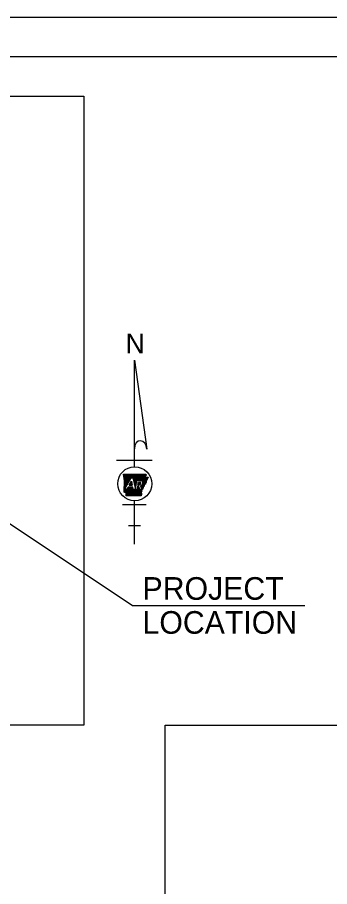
# Model space of a CAD drawing. Extents: x -0.25 to 1.92, y 0 to 0.95.
# Drawn here: x 0.3064 to 0.4721, y 0.4561 to 0.9167 of the extents above; entities that cross this region are included whole.
import ezdxf

# ---------------------------------------------------------------- set-up
doc = ezdxf.new("R2010")
doc.units = 0
for name, color, linetype in [('Default', 7, 'Continuous'), ('DSN_DRFT_DNC', 7, 'Continuous'), ('DSN_DRFT_Guideline-No-Plot', 7, 'Continuous'), ('Level 20', 7, 'Continuous'), ('Level 21', 7, 'Continuous'), ('SHET_Border-Lines', 7, 'Continuous')]:
    doc.layers.add(name, color=color, linetype=linetype)

msp = doc.modelspace()

# ---------------------------------------------------------------- linework, layer by layer
at = {"layer": 'Default'}
for q in [(0.17682, 0.73155), (0.45889, 0.60506)]:
    msp.add_line((0.36732, 0.60506), q, dxfattribs=at)
at = {"layer": 'DSN_DRFT_DNC'}
for points in [[(0.04167, 0.875), (0.34167, 0.875), (0.34167, 0.54167), (0.04167, 0.54167)], [(0.38477, 0.54167), (1.0319, 0.54167), (1.0319, 0.1443), (0.38477, 0.1443)]]:
    msp.add_lwpolyline(points, close=True, dxfattribs=at)
at = {"layer": 'DSN_DRFT_Guideline-No-Plot'}
msp.add_lwpolyline([(0, 0), (1.41667, 0), (1.41667, 0.91667), (0, 0.91667)], close=True, dxfattribs=at)
at = {"layer": 'Level 20'}
for p, q in [((0.3685, 0.73504), (0.37502, 0.68794)), ((0.3685, 0.67856), (0.3685, 0.73504)), ((0.35907, 0.68205), (0.37793, 0.68205)), ((0.36322, 0.66645), (0.36671, 0.6726)), ((0.36671, 0.6726), (0.36774, 0.6726)), ((0.36578, 0.66887), (0.36692, 0.67088)), ((0.36578, 0.66887), (0.36735, 0.66887)), ((0.36984, 0.67132), (0.37226, 0.67132)), ((0.37066, 0.66841), (0.37024, 0.66841)), ((0.37037, 0.66914), (0.3714, 0.66914)), ((0.37059, 0.67045), (0.37173, 0.67045)), ((0.37138, 0.66645), (0.37066, 0.66841)), ((0.37168, 0.66851), (0.37244, 0.66645)), ((0.36442, 0.66645), (0.36322, 0.66645)), ((0.36515, 0.66774), (0.36442, 0.66645)), ((0.36759, 0.66774), (0.36515, 0.66774)), ((0.3699, 0.66645), (0.36787, 0.66645)), ((0.37244, 0.66645), (0.37138, 0.66645)), ((0.3685, 0.63758), (0.3685, 0.6605)), ((0.36222, 0.65855), (0.37479, 0.65855)), ((0.36536, 0.64738), (0.37165, 0.64738))]:
    msp.add_line(p, q, dxfattribs=at)
for points in [[(0.36277, 0.67459), (0.36621, 0.67459), (0.36924, 0.6746), (0.3728, 0.67465), (0.37446, 0.67469)], [(0.36277, 0.6746), (0.36622, 0.67459), (0.36924, 0.6746), (0.3728, 0.67466), (0.37446, 0.67469)], [(0.36302, 0.66528), (0.36321, 0.67106), (0.36277, 0.6746)], [(0.36315, 0.66924), (0.36321, 0.67106), (0.36277, 0.67459)], [(0.36774, 0.6726), (0.36902, 0.66662), (0.36984, 0.67132)], [(0.37554, 0.67311), (0.37584, 0.6728), (0.37509, 0.67219), (0.37517, 0.67157), (0.37454, 0.67115), (0.37475, 0.6702), (0.37426, 0.66976), (0.37422, 0.66927), (0.37362, 0.66905), (0.37353, 0.66814), (0.3731, 0.66768), (0.37289, 0.66698), (0.37227, 0.66641), (0.37231, 0.6654), (0.37189, 0.66493), (0.37228, 0.66406), (0.37201, 0.6632)], [(0.37394, 0.67303), (0.37556, 0.67311)], [(0.37395, 0.67303), (0.37556, 0.67311)], [(0.36302, 0.66528), (0.36315, 0.66924)], [(0.36692, 0.67088), (0.36735, 0.66887)], [(0.37024, 0.66841), (0.3699, 0.66645)], [(0.37037, 0.66914), (0.37059, 0.67045)], [(0.37201, 0.6632), (0.3642, 0.66321), (0.3642, 0.66494)], [(0.37201, 0.6632), (0.3642, 0.66321), (0.3642, 0.66494)], [(0.36787, 0.66645), (0.36759, 0.66774)]]:
    msp.add_lwpolyline(points, dxfattribs=at)
for centre, major_axis, ratio, start_param, end_param in [((0.37176, 0.68784), (-0.00014, 0.00453), 0.719778, 4.712385, 7.768526), ((0.37115, 0.6699), (-0.000799, 0), 0.999987, 1.887169, 3.90762), ((0.37136, 0.67004), (-0.00156, 0), 0.999987, 1.777838, 4.099264)]:
    msp.add_ellipse(centre, major_axis=major_axis, ratio=ratio, start_param=start_param, end_param=end_param, dxfattribs=at)
msp.add_ellipse((0.36865, 0.66953), major_axis=(0.00903, 0), ratio=0.999976, dxfattribs=at)
for points in [[(0.37446, 0.67469), (0.37447, 0.6746), (0.3745, 0.67455), (0.3745, 0.67446), (0.37454, 0.67442), (0.3746, 0.67438), (0.37465, 0.67432), (0.37467, 0.67425), (0.37465, 0.67418), (0.37465, 0.67409), (0.37464, 0.67402), (0.37462, 0.67396), (0.37457, 0.6739), (0.37452, 0.67386), (0.37448, 0.67382), (0.37445, 0.67377), (0.37439, 0.67372), (0.37434, 0.67367), (0.37429, 0.67362), (0.37425, 0.67356), (0.37423, 0.6735), (0.37418, 0.67345), (0.37414, 0.6734), (0.37409, 0.67335), (0.37406, 0.67329), (0.37401, 0.67322), (0.374, 0.67316), (0.37397, 0.67311), (0.37397, 0.6731)], [(0.37446, 0.67469), (0.37447, 0.6746), (0.3745, 0.67455), (0.3745, 0.67446), (0.37454, 0.67442), (0.3746, 0.67439), (0.37465, 0.67432), (0.37467, 0.67425), (0.37465, 0.67418), (0.37465, 0.67409), (0.37464, 0.67402), (0.37462, 0.67395), (0.37457, 0.6739), (0.37452, 0.67386), (0.37448, 0.67382), (0.37445, 0.67377), (0.37439, 0.67372), (0.37434, 0.67367), (0.37429, 0.67362), (0.37425, 0.67356), (0.37423, 0.67349), (0.37418, 0.67345), (0.37414, 0.67341), (0.37409, 0.67335), (0.37406, 0.67329), (0.37401, 0.67322), (0.374, 0.67316), (0.37397, 0.67311), (0.37397, 0.6731)], [(0.37554, 0.67311), (0.37556, 0.67311), (0.37563, 0.67304), (0.37566, 0.67297), (0.37571, 0.67294), (0.37577, 0.67292), (0.37581, 0.67287), (0.37583, 0.67281), (0.37582, 0.67277), (0.37576, 0.67276), (0.37569, 0.67275), (0.37563, 0.67276), (0.37558, 0.67271), (0.37563, 0.67266), (0.37569, 0.6726), (0.3757, 0.67254), (0.37567, 0.67249), (0.3756, 0.67246), (0.37554, 0.67243), (0.37548, 0.67238), (0.37545, 0.67233), (0.37538, 0.67231), (0.37531, 0.67229), (0.37525, 0.67229), (0.37519, 0.67227), (0.37512, 0.67224), (0.37509, 0.67219), (0.3751, 0.67211), (0.3751, 0.67203), (0.37517, 0.672), (0.37523, 0.67199), (0.37529, 0.67196), (0.37528, 0.67192), (0.37524, 0.67186), (0.37519, 0.67181), (0.37513, 0.67179), (0.37508, 0.67174), (0.3751, 0.6717), (0.37515, 0.67167), (0.37518, 0.67162), (0.37517, 0.67157), (0.37512, 0.67154), (0.37507, 0.67155), (0.37503, 0.67161), (0.37498, 0.67162), (0.37494, 0.67164), (0.37489, 0.67162), (0.37489, 0.67155), (0.37488, 0.67149), (0.37489, 0.67144), (0.37491, 0.67137), (0.37491, 0.67132), (0.37489, 0.67125), (0.37485, 0.67117), (0.37481, 0.67115), (0.37479, 0.67123), (0.37479, 0.6713), (0.37476, 0.67134), (0.37473, 0.67134), (0.37468, 0.67131), (0.37463, 0.67126), (0.37457, 0.6712), (0.37453, 0.67115), (0.37455, 0.67108), (0.3746, 0.67107), (0.37464, 0.67108), (0.37466, 0.67112), (0.37469, 0.67113), (0.37473, 0.67106)], [(0.3738, 0.66895), (0.37373, 0.6689), (0.37369, 0.66884), (0.3735, 0.66885), (0.37351, 0.66879), (0.37344, 0.66875), (0.37338, 0.66871), (0.37342, 0.66866), (0.37348, 0.66861), (0.37354, 0.66857), (0.37358, 0.66854), (0.37359, 0.66845), (0.37361, 0.6684), (0.37363, 0.66832), (0.37364, 0.66827), (0.3736, 0.6682), (0.37355, 0.66819), (0.37351, 0.6682), (0.37345, 0.66821), (0.37341, 0.66817), (0.37337, 0.66811), (0.37334, 0.66805), (0.37332, 0.66799), (0.37329, 0.66794), (0.37325, 0.66787), (0.37319, 0.66787), (0.37312, 0.66785), (0.37308, 0.6678), (0.37309, 0.66772), (0.37313, 0.66767), (0.37316, 0.6676), (0.37318, 0.66755), (0.37317, 0.66747), (0.37314, 0.66742), (0.3731, 0.66739), (0.37308, 0.66732), (0.37305, 0.66727), (0.37303, 0.66725), (0.37298, 0.66726), (0.37292, 0.66727), (0.37288, 0.66726), (0.37283, 0.66724), (0.37279, 0.66725), (0.37274, 0.6673), (0.3727, 0.66734), (0.37266, 0.66736), (0.37261, 0.66734), (0.37261, 0.66726), (0.37263, 0.66719), (0.37265, 0.66709), (0.37263, 0.66704), (0.37262, 0.66694)], [(0.37473, 0.67106), (0.37474, 0.671), (0.3747, 0.67094), (0.37469, 0.67087), (0.37469, 0.6708), (0.37462, 0.67077), (0.37456, 0.67072), (0.3746, 0.67067), (0.37466, 0.67063), (0.37473, 0.67059), (0.37477, 0.67055), (0.37478, 0.67047), (0.37479, 0.67041), (0.37481, 0.67033), (0.37482, 0.67028), (0.37478, 0.67022), (0.37474, 0.6702), (0.37469, 0.67022), (0.37463, 0.67022), (0.37459, 0.67018), (0.37456, 0.67012), (0.37452, 0.67006), (0.3745, 0.67001), (0.37448, 0.66996), (0.37443, 0.66989), (0.37437, 0.66988), (0.3743, 0.66986), (0.37426, 0.66982), (0.37427, 0.66974), (0.37431, 0.66969), (0.37434, 0.66962), (0.37436, 0.66956), (0.37435, 0.66949), (0.37432, 0.66943), (0.37428, 0.6694), (0.37426, 0.66934), (0.37424, 0.66928), (0.37421, 0.66927), (0.37416, 0.66927), (0.3741, 0.66928), (0.37406, 0.66928), (0.37401, 0.66925), (0.37397, 0.66927), (0.37392, 0.66932), (0.37388, 0.66936), (0.37384, 0.66937), (0.37379, 0.66935), (0.37379, 0.66928), (0.37381, 0.66921), (0.37383, 0.66911), (0.37381, 0.66905), (0.3738, 0.66895)], [(0.3642, 0.66494), (0.36421, 0.66493), (0.36417, 0.66496), (0.36411, 0.66499), (0.36405, 0.66499), (0.36397, 0.665), (0.3639, 0.66501), (0.36384, 0.66505), (0.36377, 0.66501), (0.36368, 0.66497), (0.36364, 0.66501), (0.36358, 0.66498), (0.36353, 0.665), (0.36346, 0.66495), (0.36339, 0.66496), (0.36334, 0.66495), (0.36327, 0.66495), (0.36326, 0.66502), (0.3632, 0.66503), (0.36314, 0.66507), (0.36311, 0.66514), (0.36308, 0.6652), (0.36302, 0.66528)], [(0.3642, 0.66494), (0.36421, 0.66493), (0.36417, 0.66496), (0.36411, 0.66499), (0.36405, 0.66499), (0.36397, 0.665), (0.3639, 0.66501), (0.36384, 0.66505), (0.36376, 0.66501), (0.36368, 0.66497), (0.36364, 0.66501), (0.36357, 0.66498), (0.36353, 0.665), (0.36346, 0.66495), (0.36339, 0.66496), (0.36334, 0.66495), (0.36327, 0.66495), (0.36326, 0.66502), (0.3632, 0.66504), (0.36314, 0.66506), (0.36311, 0.66514), (0.36308, 0.6652), (0.36302, 0.66528)], [(0.37233, 0.66613), (0.37231, 0.66608), (0.37229, 0.666), (0.3723, 0.66593), (0.37233, 0.66587), (0.37238, 0.66583), (0.37244, 0.66578), (0.37243, 0.66571), (0.3724, 0.66568), (0.37232, 0.6657), (0.37227, 0.66573), (0.37222, 0.66571), (0.37215, 0.66568), (0.3721, 0.66567), (0.3721, 0.66557), (0.37217, 0.6655), (0.37223, 0.6655), (0.37229, 0.66549), (0.37232, 0.66541), (0.37228, 0.66535), (0.37222, 0.66532), (0.37213, 0.66536), (0.37208, 0.6654), (0.37202, 0.66543), (0.37195, 0.66545), (0.37191, 0.66544), (0.37189, 0.66536), (0.37192, 0.66527), (0.37198, 0.66522), (0.37203, 0.66515), (0.37202, 0.66509), (0.37198, 0.66508), (0.37191, 0.66506), (0.37187, 0.66504), (0.37186, 0.66502), (0.37188, 0.66495), (0.3719, 0.66487), (0.3719, 0.66481), (0.37188, 0.66476), (0.37184, 0.66467), (0.37185, 0.66462), (0.37187, 0.66459), (0.3719, 0.6646), (0.37195, 0.66463), (0.37197, 0.66466), (0.372, 0.66471), (0.37204, 0.66474), (0.3721, 0.66471), (0.37211, 0.66465), (0.37208, 0.66459), (0.37203, 0.66456), (0.37198, 0.66454), (0.37194, 0.66449), (0.37195, 0.66444), (0.37198, 0.66441), (0.37206, 0.66442), (0.37211, 0.66445), (0.37214, 0.66448), (0.37218, 0.66451), (0.3722, 0.66455), (0.37223, 0.66459), (0.37228, 0.6646), (0.3723, 0.66457), (0.37229, 0.66449), (0.37226, 0.66443), (0.37222, 0.66437), (0.37217, 0.66433), (0.37212, 0.66424), (0.37213, 0.66416), (0.37215, 0.66409), (0.37218, 0.66404), (0.37223, 0.66405), (0.37229, 0.66406), (0.37232, 0.66403), (0.37232, 0.66397), (0.37228, 0.66391), (0.37224, 0.66386), (0.37222, 0.66378), (0.37222, 0.66373), (0.37222, 0.66368), (0.37221, 0.66363), (0.37218, 0.6636), (0.3721, 0.6636), (0.37202, 0.66361), (0.37197, 0.66358), (0.37198, 0.66351), (0.37203, 0.66346), (0.37206, 0.66343), (0.37211, 0.66337), (0.37213, 0.66332), (0.37213, 0.66328), (0.37209, 0.66324), (0.37201, 0.6632)], [(0.37233, 0.66613), (0.37231, 0.66608), (0.37229, 0.666), (0.3723, 0.66593), (0.37233, 0.66587), (0.37238, 0.66583), (0.37244, 0.66578), (0.37243, 0.66571), (0.3724, 0.66568), (0.37232, 0.6657), (0.37227, 0.66573), (0.37222, 0.66571), (0.37215, 0.66568), (0.3721, 0.66567), (0.3721, 0.66557), (0.37217, 0.6655), (0.37223, 0.6655), (0.37229, 0.66549), (0.37232, 0.66541), (0.37228, 0.66535), (0.37222, 0.66532), (0.37213, 0.66536), (0.37208, 0.6654), (0.37202, 0.66543), (0.37195, 0.66545), (0.37191, 0.66544), (0.37189, 0.66536), (0.37192, 0.66527), (0.37198, 0.66522), (0.37203, 0.66515), (0.37202, 0.66509), (0.37198, 0.66508), (0.37191, 0.66506), (0.37187, 0.66504), (0.37186, 0.66502), (0.37188, 0.66495), (0.3719, 0.66487), (0.3719, 0.66481), (0.37188, 0.66476), (0.37184, 0.66467), (0.37185, 0.66462), (0.37187, 0.66459), (0.3719, 0.6646), (0.37195, 0.66463), (0.37197, 0.66466), (0.372, 0.66471), (0.37204, 0.66474), (0.3721, 0.66471), (0.37211, 0.66465), (0.37208, 0.66459), (0.37203, 0.66456), (0.37198, 0.66454), (0.37194, 0.66449), (0.37195, 0.66444), (0.37198, 0.66441), (0.37206, 0.66442), (0.37211, 0.66445), (0.37214, 0.66448), (0.37218, 0.66451), (0.3722, 0.66455), (0.37223, 0.66459), (0.37228, 0.6646), (0.3723, 0.66457), (0.37229, 0.66449), (0.37226, 0.66443), (0.37222, 0.66437), (0.37217, 0.66433), (0.37212, 0.66424), (0.37213, 0.66416), (0.37215, 0.66409), (0.37218, 0.66404), (0.37223, 0.66405), (0.37229, 0.66406), (0.37232, 0.66403), (0.37232, 0.66397), (0.37228, 0.66391), (0.37224, 0.66386), (0.37222, 0.66378), (0.37222, 0.66373), (0.37222, 0.66368), (0.37221, 0.66363), (0.37218, 0.6636), (0.3721, 0.6636), (0.37202, 0.66361), (0.37197, 0.66358), (0.37198, 0.66351), (0.37203, 0.66346), (0.37206, 0.66343), (0.37211, 0.66337), (0.37213, 0.66332), (0.37213, 0.66328), (0.37209, 0.66324), (0.37201, 0.6632)], [(0.37262, 0.66694), (0.37262, 0.66693), (0.37258, 0.66688), (0.3726, 0.66681), (0.37268, 0.66678), (0.37272, 0.66671), (0.37272, 0.66664), (0.3727, 0.66656), (0.37266, 0.66652), (0.37258, 0.6665), (0.37252, 0.66649), (0.37252, 0.66639), (0.37249, 0.66634), (0.37245, 0.66633), (0.37238, 0.66636), (0.37234, 0.66637), (0.3723, 0.6664), (0.37224, 0.66643), (0.37219, 0.66642), (0.3722, 0.66633), (0.37221, 0.66633), (0.37226, 0.66626), (0.37231, 0.6662), (0.37233, 0.66613)], [(0.37262, 0.66694), (0.37262, 0.66693), (0.37258, 0.66688), (0.3726, 0.66681), (0.37268, 0.66678), (0.37272, 0.66671), (0.37272, 0.66664), (0.3727, 0.66656), (0.37266, 0.66652), (0.37258, 0.6665), (0.37252, 0.66649), (0.37252, 0.66639), (0.37249, 0.66634), (0.37245, 0.66633), (0.37238, 0.66636), (0.37234, 0.66637), (0.3723, 0.6664), (0.37224, 0.66643), (0.37219, 0.66642), (0.3722, 0.66633), (0.37221, 0.66633), (0.37226, 0.66626), (0.37231, 0.6662), (0.37233, 0.66613)]]:
    msp.add_spline(points, degree=3, dxfattribs=at)
at = {"layer": 'Level 21'}
for p, q in [((0.36278, 0.67452), (0.36286, 0.6746)), ((0.36281, 0.6743), (0.36311, 0.6746)), ((0.36284, 0.67407), (0.36336, 0.6746)), ((0.36286, 0.67385), (0.36361, 0.6746)), ((0.36289, 0.67363), (0.36386, 0.6746)), ((0.36292, 0.67341), (0.36411, 0.6746)), ((0.36295, 0.67319), (0.36436, 0.67459)), ((0.36297, 0.67296), (0.36461, 0.67459)), ((0.363, 0.67274), (0.36486, 0.67459)), ((0.36303, 0.67252), (0.3651, 0.67459)), ((0.36306, 0.6723), (0.36535, 0.67459)), ((0.36309, 0.67208), (0.3656, 0.67459)), ((0.36311, 0.67185), (0.36585, 0.67459)), ((0.36314, 0.67163), (0.3661, 0.67459)), ((0.36315, 0.66914), (0.3686, 0.6746)), ((0.36316, 0.6694), (0.36835, 0.6746)), ((0.36317, 0.66966), (0.3681, 0.6746)), ((0.36317, 0.66992), (0.36785, 0.6746)), ((0.36317, 0.67141), (0.36635, 0.67459)), ((0.36318, 0.67018), (0.3676, 0.6746)), ((0.36319, 0.67044), (0.36735, 0.6746)), ((0.3632, 0.67069), (0.3671, 0.6746)), ((0.3632, 0.67119), (0.3666, 0.67459)), ((0.36321, 0.67095), (0.36685, 0.6746)), ((0.36686, 0.6726), (0.36885, 0.6746)), ((0.36711, 0.6726), (0.3691, 0.6746)), ((0.36736, 0.6726), (0.36936, 0.6746)), ((0.36761, 0.6726), (0.36961, 0.67461)), ((0.36776, 0.67251), (0.36986, 0.67461)), ((0.3678, 0.6723), (0.37012, 0.67461)), ((0.36785, 0.6721), (0.37037, 0.67462)), ((0.36789, 0.67189), (0.37062, 0.67462)), ((0.36794, 0.67168), (0.37088, 0.67463)), ((0.36798, 0.67148), (0.37113, 0.67463)), ((0.36802, 0.67127), (0.37138, 0.67463)), ((0.36807, 0.67107), (0.37164, 0.67464)), ((0.36811, 0.67086), (0.37189, 0.67464)), ((0.36816, 0.67066), (0.37215, 0.67465)), ((0.3682, 0.67045), (0.3724, 0.67465)), ((0.36824, 0.67025), (0.37265, 0.67465)), ((0.36829, 0.67004), (0.37291, 0.67466)), ((0.36833, 0.66983), (0.37316, 0.67466)), ((0.37007, 0.67132), (0.37342, 0.67467)), ((0.37032, 0.67132), (0.37367, 0.67468)), ((0.37057, 0.67132), (0.37393, 0.67468)), ((0.37082, 0.67132), (0.37418, 0.67469)), ((0.37107, 0.67132), (0.37444, 0.67469)), ((0.37131, 0.67132), (0.3745, 0.6745)), ((0.37156, 0.67132), (0.37462, 0.67437)), ((0.37181, 0.67132), (0.37465, 0.67415)), ((0.37206, 0.67132), (0.37408, 0.67333)), ((0.37229, 0.6713), (0.37403, 0.67303)), ((0.37243, 0.67118), (0.37429, 0.67305)), ((0.37255, 0.67105), (0.37456, 0.67306)), ((0.37266, 0.67091), (0.37482, 0.67308)), ((0.37275, 0.67076), (0.37508, 0.67309)), ((0.37283, 0.67058), (0.37535, 0.6731)), ((0.37288, 0.67039), (0.37558, 0.67309)), ((0.37292, 0.67017), (0.3757, 0.67296)), ((0.37559, 0.6726), (0.37582, 0.67282)), ((0.36308, 0.66708), (0.36423, 0.66823)), ((0.36309, 0.66734), (0.36455, 0.6688)), ((0.3631, 0.6676), (0.36488, 0.66938)), ((0.36311, 0.66811), (0.36553, 0.67053)), ((0.36311, 0.66785), (0.36521, 0.66995)), ((0.36312, 0.66837), (0.36586, 0.6711)), ((0.36313, 0.66863), (0.36618, 0.67168)), ((0.36314, 0.66889), (0.36651, 0.67225)), ((0.3658, 0.66887), (0.36708, 0.67015)), ((0.36605, 0.66887), (0.36712, 0.66994)), ((0.3661, 0.66941), (0.36704, 0.67035)), ((0.3663, 0.66887), (0.36717, 0.66974)), ((0.36642, 0.66999), (0.36699, 0.67056)), ((0.36655, 0.66887), (0.36721, 0.66953)), ((0.36675, 0.67056), (0.36695, 0.67077)), ((0.3668, 0.66887), (0.36726, 0.66933)), ((0.36705, 0.66887), (0.3673, 0.66912)), ((0.36729, 0.66887), (0.36734, 0.66891)), ((0.36838, 0.66963), (0.36979, 0.67105)), ((0.36842, 0.66942), (0.36974, 0.67074)), ((0.36846, 0.66922), (0.36969, 0.67044)), ((0.36851, 0.66901), (0.36964, 0.67014)), ((0.36855, 0.66881), (0.36958, 0.66984)), ((0.3686, 0.6686), (0.36953, 0.66953)), ((0.36864, 0.66839), (0.36948, 0.66923)), ((0.36868, 0.66819), (0.36942, 0.66893)), ((0.36873, 0.66798), (0.36937, 0.66863)), ((0.36877, 0.66778), (0.36932, 0.66832)), ((0.36882, 0.66757), (0.36927, 0.66802)), ((0.36999, 0.667), (0.37086, 0.66787)), ((0.37005, 0.6673), (0.37079, 0.66805)), ((0.3701, 0.66761), (0.37072, 0.66823)), ((0.37015, 0.66791), (0.37065, 0.66841)), ((0.3702, 0.66821), (0.3704, 0.66841)), ((0.37037, 0.66914), (0.37168, 0.67045)), ((0.37042, 0.66944), (0.37143, 0.67045)), ((0.37047, 0.66974), (0.37118, 0.67045)), ((0.37052, 0.67004), (0.37093, 0.67045)), ((0.37058, 0.67035), (0.37068, 0.67045)), ((0.37062, 0.66914), (0.37182, 0.67034)), ((0.37087, 0.66914), (0.3719, 0.67017)), ((0.37112, 0.66914), (0.37195, 0.66997)), ((0.37137, 0.66914), (0.37193, 0.6697)), ((0.3717, 0.66846), (0.37178, 0.66854)), ((0.37177, 0.66828), (0.37224, 0.66875)), ((0.37184, 0.66809), (0.3746, 0.67086)), ((0.3719, 0.66791), (0.37465, 0.67066)), ((0.37197, 0.66773), (0.3747, 0.67046)), ((0.37204, 0.66755), (0.37474, 0.67025)), ((0.3721, 0.66737), (0.3736, 0.66886)), ((0.37217, 0.66718), (0.37357, 0.66859)), ((0.37224, 0.667), (0.37355, 0.66831)), ((0.37265, 0.66916), (0.37456, 0.67107)), ((0.37287, 0.66962), (0.37513, 0.67189)), ((0.37292, 0.66993), (0.3751, 0.67211)), ((0.37389, 0.66915), (0.37424, 0.6695)), ((0.37485, 0.67136), (0.37516, 0.67167)), ((0.36302, 0.66528), (0.3642, 0.66645)), ((0.36303, 0.66553), (0.36395, 0.66645)), ((0.36304, 0.66579), (0.3637, 0.66645)), ((0.36305, 0.6663), (0.36325, 0.6665)), ((0.36305, 0.66605), (0.36345, 0.66645)), ((0.36306, 0.66656), (0.36358, 0.66707)), ((0.36307, 0.66682), (0.3639, 0.66765)), ((0.36312, 0.66512), (0.36574, 0.66774)), ((0.36327, 0.66502), (0.36599, 0.66774)), ((0.36345, 0.66495), (0.36624, 0.66774)), ((0.36374, 0.66499), (0.36649, 0.66774)), ((0.364, 0.665), (0.36674, 0.66774)), ((0.36419, 0.66494), (0.36699, 0.66774)), ((0.3642, 0.66445), (0.36749, 0.66774)), ((0.3642, 0.6647), (0.36724, 0.66774)), ((0.3642, 0.6642), (0.36762, 0.66762)), ((0.3642, 0.66396), (0.36766, 0.66742)), ((0.3642, 0.66371), (0.36771, 0.66721)), ((0.3642, 0.66346), (0.36775, 0.66701)), ((0.36421, 0.66321), (0.3678, 0.6668)), ((0.36446, 0.66321), (0.36784, 0.6666)), ((0.3647, 0.66695), (0.36549, 0.66774)), ((0.3647, 0.66321), (0.36795, 0.66645)), ((0.36495, 0.66321), (0.3682, 0.66645)), ((0.36503, 0.66753), (0.36524, 0.66774)), ((0.3652, 0.66321), (0.36844, 0.66645)), ((0.36545, 0.66321), (0.36869, 0.66645)), ((0.3657, 0.66321), (0.36894, 0.66645)), ((0.36595, 0.66321), (0.36919, 0.66645)), ((0.3662, 0.66321), (0.36944, 0.66645)), ((0.36645, 0.66321), (0.36969, 0.66645)), ((0.3667, 0.66321), (0.37099, 0.6675)), ((0.36695, 0.66321), (0.37106, 0.66732)), ((0.3672, 0.66321), (0.37113, 0.66714)), ((0.36745, 0.66321), (0.37119, 0.66695)), ((0.3677, 0.66321), (0.37126, 0.66677)), ((0.36794, 0.66321), (0.37133, 0.66659)), ((0.36819, 0.66321), (0.37144, 0.66645)), ((0.36844, 0.66321), (0.37169, 0.66645)), ((0.36869, 0.6632), (0.37194, 0.66645)), ((0.36886, 0.66737), (0.36921, 0.66772)), ((0.3689, 0.66716), (0.36916, 0.66742)), ((0.36894, 0.6632), (0.37219, 0.66645)), ((0.36895, 0.66696), (0.36911, 0.66712)), ((0.36899, 0.66675), (0.36906, 0.66681)), ((0.36919, 0.6632), (0.37227, 0.66629)), ((0.36944, 0.6632), (0.37228, 0.66605)), ((0.36969, 0.6632), (0.3723, 0.66581)), ((0.36994, 0.6667), (0.37093, 0.66768)), ((0.36994, 0.6632), (0.37231, 0.66557)), ((0.37019, 0.6632), (0.3719, 0.66491)), ((0.37044, 0.6632), (0.37197, 0.66474)), ((0.37069, 0.6632), (0.37205, 0.66457)), ((0.37094, 0.6632), (0.37213, 0.66439)), ((0.37118, 0.6632), (0.3722, 0.66422)), ((0.37143, 0.6632), (0.37227, 0.66404)), ((0.37168, 0.6632), (0.37216, 0.66367)), ((0.37193, 0.6632), (0.37204, 0.66331)), ((0.37231, 0.66682), (0.37307, 0.66758)), ((0.37237, 0.66664), (0.37297, 0.66723))]:
    msp.add_line(p, q, dxfattribs=at)
at = {"layer": 'SHET_Border-Lines'}
msp.add_lwpolyline([(0.02083, 0.02083), (1.39583, 0.02083), (1.39583, 0.89583), (0.02083, 0.89583)], close=True, dxfattribs=at)

# ---------------------------------------------------------------- texts
at = {"layer": 'Default'}
for s, p in [('PROJECT', (0.3728, 0.60806)), ('LOCATION', (0.3728, 0.59006))]:
    msp.add_text(s, height=0.012, dxfattribs=at).set_placement(p)
at = {"layer": 'Level 20'}
for s, height, p in [('N', 0.01051, (0.36382, 0.73859)), ('STS 10-03-17', 0.0002612, (0.36779, 0.66057))]:
    msp.add_text(s, height=height, dxfattribs=at).set_placement(p)

doc.saveas('drawing.dxf')
